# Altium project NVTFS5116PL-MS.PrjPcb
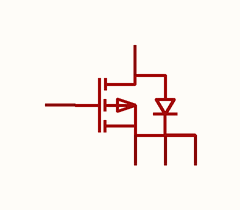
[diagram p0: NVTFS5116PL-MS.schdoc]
1 sheet, 1 parts. Net scope: global (net labels, ports and power ports of the same name join across sheets).

## Sheet NVTFS5116PL-MS.schdoc
size 127 x 101 mm

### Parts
Q?  nvtfs5116pl-ms  [POWERDI3333-8_DMN7022LFGQ-7]  (value not drawn)

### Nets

Not connected (* = marked no-connect by the designer): Q? 1(S) 2(S) 3(S) 4(G) 5(D)

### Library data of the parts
Q? = nvtfs5116pl-ms: 数量:1个P沟道;漏源电压(Vdss):60V;连续漏极电流(Id):20A;导通电阻(RDS(on)):90mΩ@4.5V;耗散功率(Pd):25W;阈值电压(Vgs(th)):2.5V;; Manufacturer: MSKSEMI(美森科); AddInBom: yes; ModelId: 296e462280334ba794f41fc0f4558c2c; ModelTransform: 130.708,130.708,0,0,0,0,0,18.625,0; Number: 1个P沟道; Drain to Source Voltage: 60V; Current - Continuous Drain(Id): 20A; Pd - Power Dissipation: 25W; Gate Threshold Voltage (Vgs(th)): 2.5V; Gate Charge(Qg): 6.1nC@4.5V; Input Capacitance(Ciss): 585pF; Type: P沟道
